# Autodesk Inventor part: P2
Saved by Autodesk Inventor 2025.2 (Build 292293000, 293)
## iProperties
Created: 2025-04
Part Number: P2
Material: Generic
Description: NOT SPECIFIED
Document SubType Name: Modeling
Designer: BennF
Density: 1 g/cm^3
Appearance: Default
Author: BennF
Revision Number: 2LAST_VERSION
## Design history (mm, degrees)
feature "Base1"
body "Solid1"
